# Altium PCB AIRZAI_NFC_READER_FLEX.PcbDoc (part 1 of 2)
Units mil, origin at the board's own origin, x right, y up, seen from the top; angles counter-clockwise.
Board outline 2897.24 x 5925.59 mil, 2 copper layers (Top Layer, Bottom Layer); 45 components, 43 nets, 193 pads, 92 vias.
Unrouted connection lines stored in the file: 129.
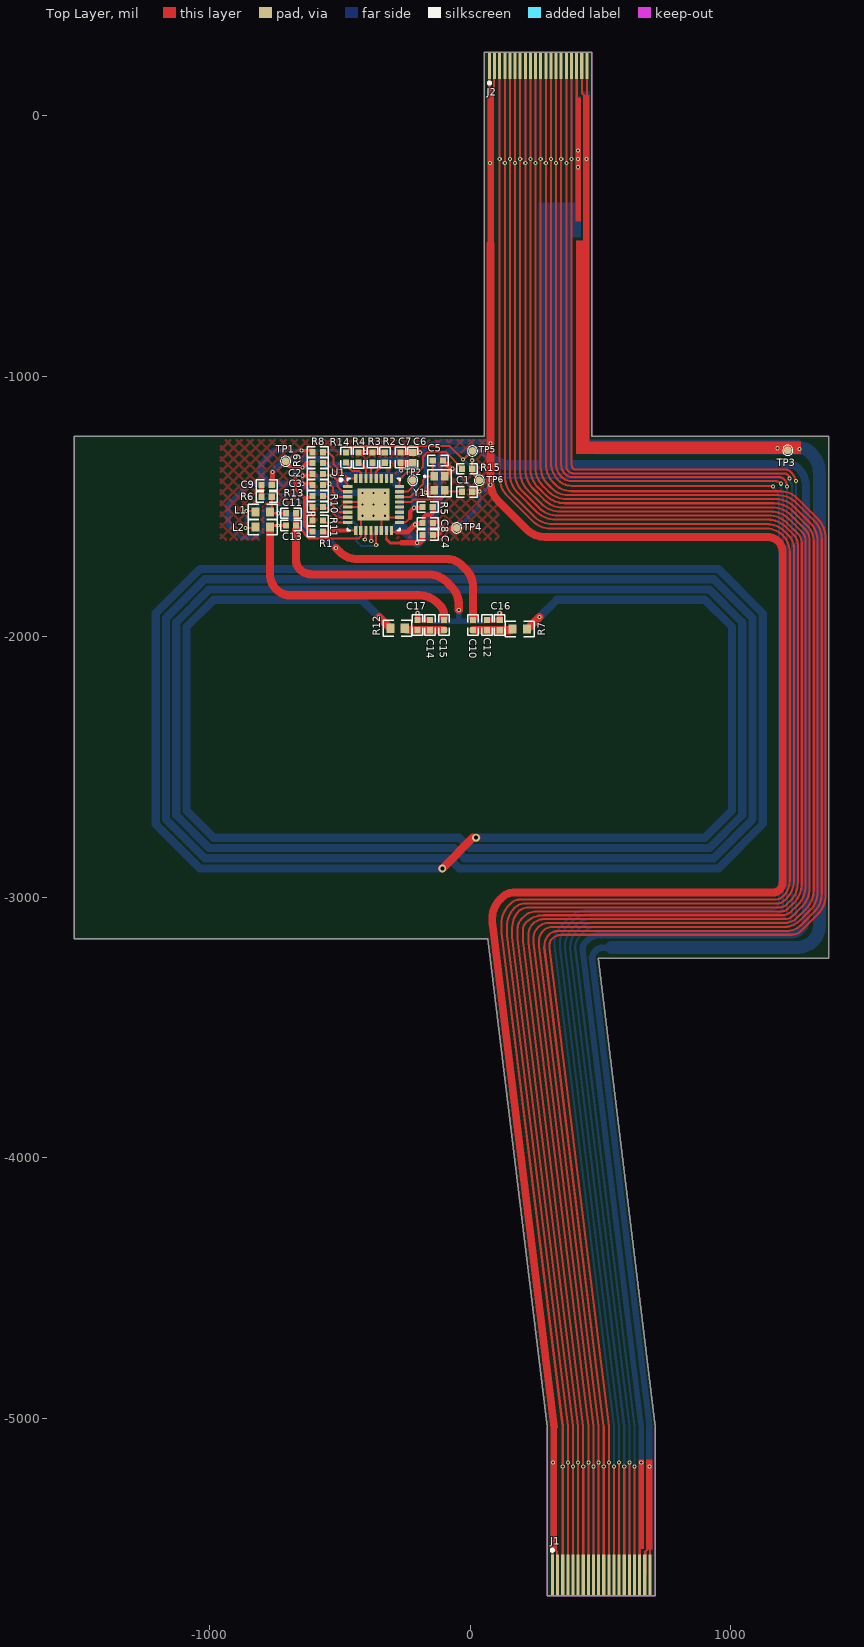
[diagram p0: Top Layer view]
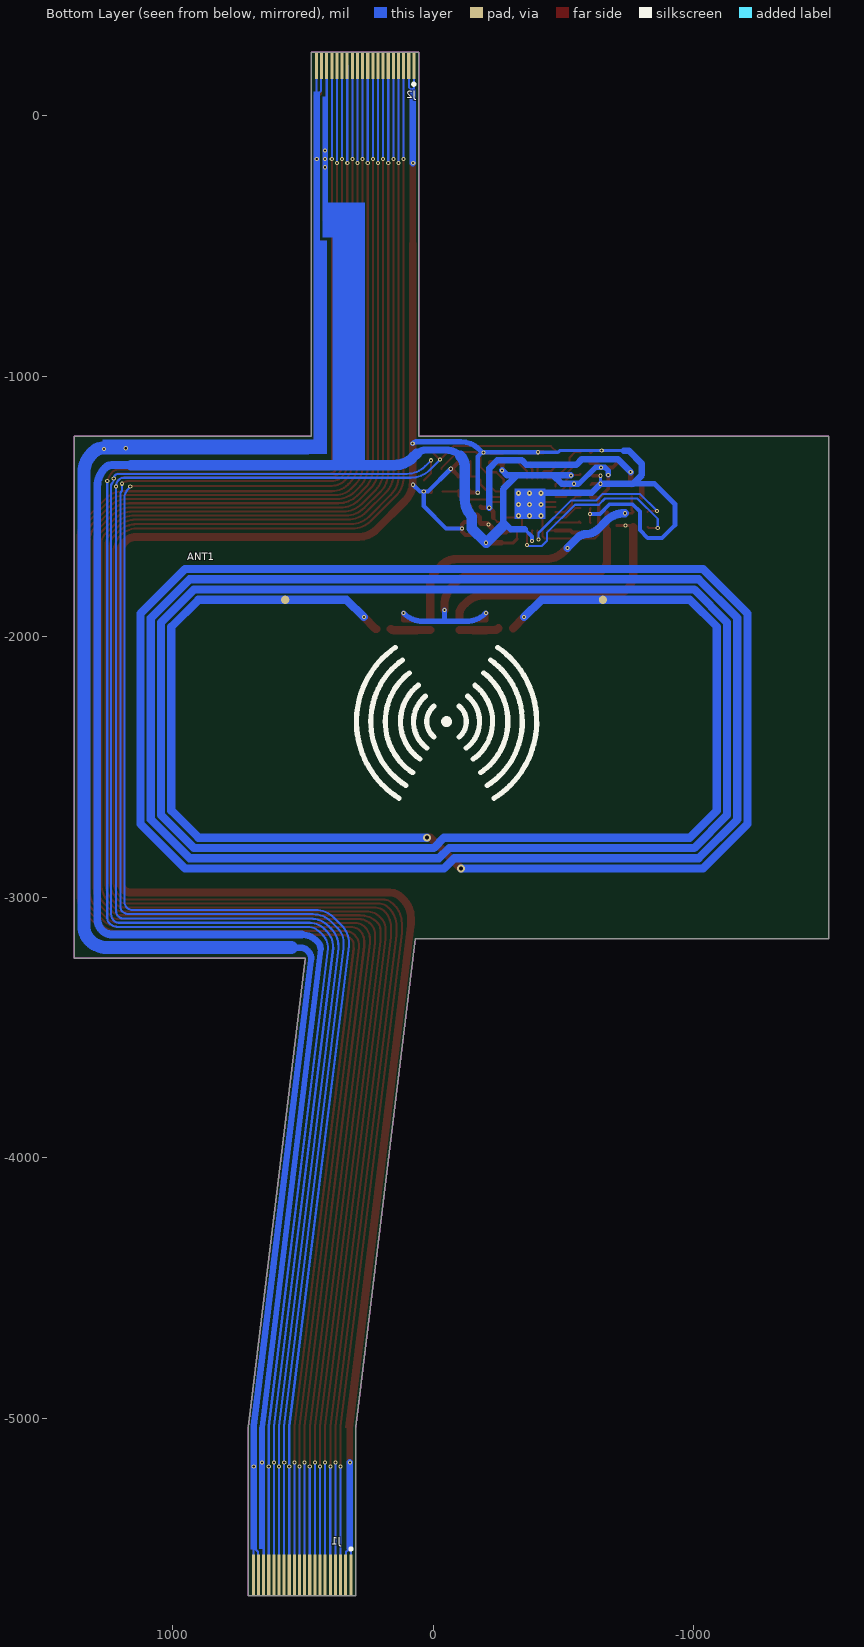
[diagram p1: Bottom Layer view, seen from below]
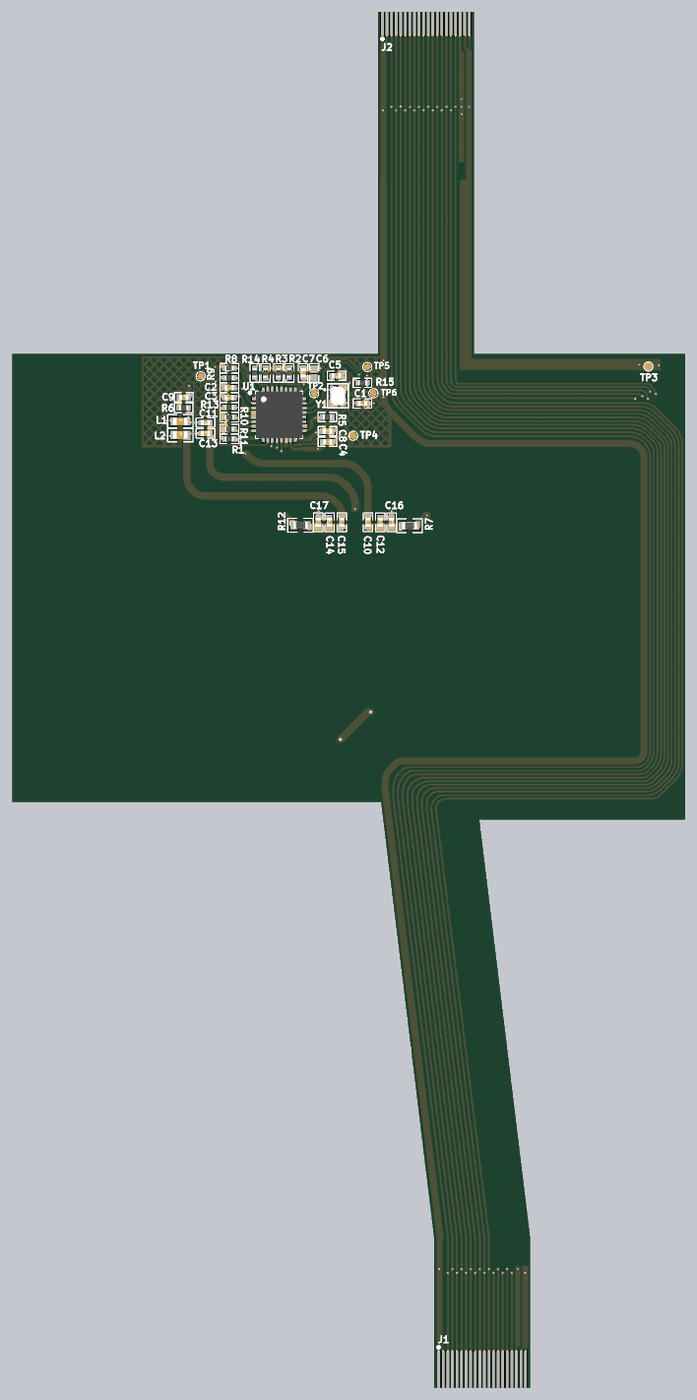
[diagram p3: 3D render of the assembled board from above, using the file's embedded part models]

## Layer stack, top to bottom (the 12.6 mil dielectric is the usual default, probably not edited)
Top Solder: solder mask 0.4, Solder Resist, Dk 3.5
Top Layer: signal copper 1.4
Dielectric 1: dielectric 12.6, FR-4, Dk 4.8
Bottom Layer: signal copper 1.4
Bottom Solder: solder mask 0.4, Solder Resist, Dk 3.5

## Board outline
-1519.83,-3158.65 -1519.83,-1229.53 54.19,-1229.53 54.19,244.09 467.57,244.09 467.57,-1229.53 1377.42,-1229.53 1377.42,-3233.99 490.88,-3233.99 490.88,-3234.01 709.7,-5033.99 709.7,-5681.5 296.31,-5681.5 296.31,-5033.99 68.33,-3158.64 68.32,-3158.65

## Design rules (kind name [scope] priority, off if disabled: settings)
Clearance Clearance_polygon_5V [OnLayer('Keep-Out Layer') vs (InNet('+5V') AND InPolygon)] p1: gap=10 ignorepadtopadclearanceinfootprint=FALSE
Clearance Clearance_POLYGON_KEEPOUT [(OnLayer('Keep-Out Layer')) vs (InNet('GND') AND InPolygon)] p2: gap=10 ignorepadtopadclearanceinfootprint=FALSE
Clearance [All] p3: gap=6 ignorepadtopadclearanceinfootprint=FALSE
MinimumSolderMaskSliver [All] p1: minsoldermaskwidth=1
PolygonConnect [All] p1: connectstyle=Direct reliefconductorwidth=10 reliefentries=4 polygonreliefangle="90 Angle" airgapwidth=10
RoomDefinition AIRZAI_NFC_READER_FLEX [InComponentClass('AIRZAI_NFC_READER_FLEX')] p1: confinementstyle=ConfineIn formatcopy=TRUE lockcomponents=FALSE outline -16741.56,-18457.69 14188.31,-18457.69 14188.31,4099.5 -16741.56,4099.5
RoutingVias [All] p1: holewidth=28 width=50 viastyle="Through Hole" minholewidth=8 minwidth=16 maxholewidth=28 maxwidth=50
SilkToSilkClearance [All] p1: silktosilkclearance=1
SilkToSolderMaskClearance [IsPad] p1: minsilkscreentomaskgap=2 clearancetoexposedcopper=TRUE
SolderMaskExpansion [All] p1: expansion=4
UnRoutedNet [All] p1: checkbadconnections=TRUE
Width [All] p1: maxlimit=100 minlimit=6 preferedwidth=10
26 further rules are at their usual default settings.

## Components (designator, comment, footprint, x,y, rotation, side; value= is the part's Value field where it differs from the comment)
ANT1 "NFC_ANT" ANTENNA-NFC-60MMX30MM -42.1,-2314.54 r180 bottom locked
C1 "12pF" 0402CAP -12,-1443.17 r180 top
C2 "0.1µF" 0402CAP -585.45,-1375.04 r180 top
C3 "0.1µF" 0402CAP -585.45,-1417.72 r180 top
C4 "0.1µF" 0402CAP -162.78,-1608.61 r0 top
C5 "12pF" 0402CAP -123.89,-1323.43 r180 top
C6 "1uF" CAPC0402(1005)60_M -220.58,-1311.81 r270 top
C7 "0.1µF" 0402CAP -267.8,-1311.69 r90 top
C8 "0.1µF" 0402CAP -162.78,-1562.61 r0 top
C9 "1nF" 0402CAP -781.38,-1416.43 r0 top
C10 "18pF" 0402CAP 11.31,-1954.52 r90 top
C11 "220pF" 0402CAP -687.95,-1525.43 r180 top
C12 "47pF" 0402CAP 64.22,-1954.87 r270 top
C13 "220pF" 0402CAP -687.95,-1572.43 r0 top
C14 "47pF" 0402CAP -154.1,-1954.87 r90 top
C15 "18pF" 0402CAP -100.99,-1954.68 r90 top
C16 "DNP" 0402CAP 113.24,-1954.86 r270 top
C17 "DNP" 0402CAP -202.78,-1954.68 r90 top
J1 "FFC Cable" FFC_PADS_MBD 493.17,-5602.76 r180 top locked
J2 "FFC Cable" FFC_PADS_LID 251.04,192.91 r180 top locked
L1 "560nH" 0603CAP -796.38,-1520.43 r0 top
L2 "560mH" 0603CAP -796.38,-1578.43 r0 top
R1 "0R" 0402 -585.42,-1595.88 r180 top
R2 "10K" 0402 -327.8,-1311.69 r270 top
R3 "10K" 0402 -374.8,-1311.69 r270 top
R4 "10K" 0402 -429.42,-1311.88 r270 top
R5 "1K" 0402 -163.26,-1501.15 r180 top
R6 "2.7K" 0402 -781.7,-1462.43 r180 top
R7 "3.3" 0603 190.22,-1969.52 r180 top
R8 "10K" 0402 -585.42,-1291.1 r180 top
R9 "10K" 0402 -585.42,-1332.88 r180 top
R10 "0R" 0402 -585.26,-1501.88 r180 top
R11 "0R" 0402 -585.42,-1552.88 r180 top
R12 "3.3" 0603 -278.78,-1967.3 r0 top
R13 "10K" 0402 -585.42,-1459.88 r180 top
R14 "0R" 0402 -476.42,-1311.62 r90 top
R15 "0R" 0402 -12,-1354.57 r0 top
TP1 "WIREPT" TP_0.9MM -708.8,-1325.99 r90 top
TP2 "WIREPT" TP_0.9MM -220.42,-1398.88 r270 top
TP3 "WIREPT" TP_0.9MM 1219,-1283.99 r90 top
TP4 "WIREPT" TP_0.9MM -52,-1581.99 r90 top
TP5 "WIREPT" TP_0.9MM 8.85,-1286.31 r90 top
TP6 "WIREPT" TP_0.9MM 35,-1399.17 r90 top
U1 "MFRC52202HN1,115" VFQFN-32-MFRC52202HN1,157 -370.78,-1491.88 r0 top
Y1 "27.12MHz" XTAL_2016 -117.78,-1410.57 r270 top

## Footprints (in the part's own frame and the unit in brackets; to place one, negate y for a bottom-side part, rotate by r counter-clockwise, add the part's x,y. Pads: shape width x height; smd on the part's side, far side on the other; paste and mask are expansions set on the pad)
0402 [mm] "Chip Resistor, Body 1.1x0.5mm, IPC High Density"
  rect 0.6x0.6 smd: 1(-0.5,0) 2(0.5,0)
  silkscreen extent -1.02,-0.51 1.02,0.51, body extent -0.5,-0.25 0.5,0.25, height 0.27
0402CAP [mm] "Chip Capacitor, Body 1.1x0.5mm, IPC High Density"
  rect 0.6x0.6 smd: 1(-0.5,0) 2(0.5,0)
  silkscreen extent -1.02,-0.51 1.02,0.51, body extent -0.5,-0.3 0.5,0.3, height 0.19
0603 [mm] "Chip Resistor, Body 1.6x0.8mm, IPC High Density"
  rect 0.8x0.9 smd: 1(-0.7,0) 2(0.7,0)
  silkscreen extent -1.4,-0.76 1.4,0.76, body extent -0.8,-0.41 0.8,0.4, height 0.37
0603CAP [mm] "Chip Capacitor, Body 1.6x0.8mm, IPC High Density"
  rect 0.8x0.9 smd: 1(-0.7,0) 2(0.7,0)
  silkscreen extent -1.4,-0.76 1.4,0.76, body extent -0.8,-0.4 0.8,0.4, height 0.29
ANTENNA-NFC-60MMX30MM [mm] "ANTENNA-ID2+10P-01"
  round 0.8 smd paste-0.8: 1(-15.494,11.6) 2(15.494,11.6)
  Top Layer lines w0.8: 15.494,11.6 23.97,11.6 26.6,8.97 26.6,-8.97 23.97,-11.6 0,-11.6 -1,-12.6 -24.404,-12.6 -27.6,-9.404 -27.6,9.404 -24.404,12.6 24.404,12.6 27.6,9.404 27.6,-9.404 24.404,-12.6 0.508,-12.6 -0.492,-13.6 -24.838,-13.6 -28.6,-9.838 -28.6,9.838 -24.838,13.6 24.838,13.6 28.6,9.838 28.6,-9.838 24.838,-13.6 1,-13.6 0,-14.6 -25.272,-14.6 -29.6,-10.272 -29.6,10.272 -25.272,14.6 25.272,14.6 29.6,10.272 29.6,-10.272 25.272,-14.6 1.651,-14.6 ; -1.651,-11.6 -23.97,-11.6 -26.6,-8.97 -26.6,8.97 -23.97,11.6 -15.494,11.6
  Bottom Layer lines w0.8: 1.651,-14.6 -1.349,-11.6 -1.651,-11.6
CAPC0402(1005)60_M [mm] "Chip Capacitor, Body 1.0x0.5mm, Height 0.6mm, IPC Low Density"
  rect 0.72x0.72 smd: 1(-0.5,0) 2(0.5,0)
  silkscreen extent -1.02,-0.51 1.02,0.51, body extent -0.55,-0.3 0.55,0.3, height 0.6
FFC_PADS_LID [mm] "(0.50mm"
  rect 0.3x2.6 smd: 1(4.5,0) 2(4,0) 3(3.5,0) 4(3,0) 5(2.5,0) 6(2,0) 7(1.5,0) 8(1,0) 9(0.5,0) 10(0,0) 11(-0.5,0) 12(-1,0) 13(-1.5,0) 14(-2,0) 15(-2.5,0) 16(-3,0) 17(-3.5,0) 18(-4,0) 19(-4.5,0) 20(-5,0)
  rect 0.3x2.6 smd far side: 1(4.5,0) 2(4,0) 3(3.5,0) 4(3,0) 5(2.5,0) 6(2,0) 7(1.5,0) 8(1,0) 9(0.5,0) 10(0,0) 11(-0.5,0) 12(-1,0) 13(-1.5,0) 14(-2,0) 15(-2.5,0) 16(-3,0) 17(-3.5,0) 18(-4,0) 19(-4.5,0) 20(-5,0)
  silkscreen extent 4.37,1.58 4.62,1.83
FFC_PADS_MBD [mm] "(0.50mm"
  rect 0.3x4 smd: 1(4.5,0) 2(4,0) 3(3.5,0) 4(3,0) 5(2.5,0) 6(2,0) 7(1.5,0) 8(1,0) 9(0.5,0) 10(0,0) 11(-0.5,0) 12(-1,0) 13(-1.5,0) 14(-2,0) 15(-2.5,0) 16(-3,0) 17(-3.5,0) 18(-4,0) 19(-4.5,0) 20(-5,0)
  rect 0.3x4 smd far side: 1(4.5,0) 2(4,0) 3(3.5,0) 4(3,0) 5(2.5,0) 6(2,0) 7(1.5,0) 8(1,0) 9(0.5,0) 10(0,0) 11(-0.5,0) 12(-1,0) 13(-1.5,0) 14(-2,0) 15(-2.5,0) 16(-3,0) 17(-3.5,0) 18(-4,0) 19(-4.5,0) 20(-5,0)
  silkscreen extent 4.39,-2.56 4.64,-2.31
TP_0.9MM [mm] "0.9MM DIA TESTPOINT"
  round 0.75 smd paste-5 mask+0.05: 1(0,0)
  silkscreen extent -0.5,-0.5 0.5,0.5
VFQFN-32-MFRC52202HN1,157 [mm]
  rect 0.9x0.31 smd: 1(-2.529,1.75) 2(-2.529,1.25) 3(-2.529,0.75) 4(-2.529,0.25) 5(-2.529,-0.25) 6(-2.529,-0.75) 7(-2.529,-1.25) 8(-2.529,-1.75) 17(2.529,-1.75) 18(2.529,-1.25) 19(2.529,-0.75) 20(2.529,-0.25) 21(2.529,0.25) 22(2.529,0.75) 23(2.529,1.25) 24(2.529,1.75)
  rect 0.31x0.9 smd: 9(-1.75,-2.529) 10(-1.25,-2.529) 11(-0.75,-2.529) 12(-0.25,-2.529) 13(0.25,-2.529) 14(0.75,-2.529) 15(1.25,-2.529) 16(1.75,-2.529) 25(1.75,2.529) 26(1.25,2.529) 27(0.75,2.529) 28(0.25,2.529) 29(-0.25,2.529) 30(-0.75,2.529) 31(-1.25,2.529) 32(-1.75,2.529)
  rect 3.1x3.1 smd: 33(0,0)
  silkscreen extent -3.32,-2.55 2.55,2.55, body extent -2.55,-2.55 2.55,2.55, height 1
XTAL_2016 [mm] "2.00mm x 1.60mm"
  rect 0.85x0.75 smd: 1(-0.675,-0.525) 2(0.675,-0.525) 3(0.675,0.525) 4(-0.675,0.525)
  silkscreen extent -1.32,-1.47 1.32,1.14, body extent -1,-0.81 1,0.79, height 0.65

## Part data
C1 C5: library part CAP, "CAP CER 12PF 50V C0G/NP0 0402", Case/Package=0402, Case Code (Metric)=1005, Dielectric=C0G, Dielectric Material=Ceramic, Manufacturer=KEMET, Manufacturer Part Number=C0402C120J5GACTU, Max Operating Temperature=125°C, Min Operating Temperature=-55°C, Package Quantity=1, Supplier Part Number 1=399-1013-6-ND, Temperature Coefficient=30ppm/°C, Tolerance=5%, Voltage=50V
C2 C3 C4 C7 C8: library part C0402-100n, "Capacitor, X7R, ±10%", Case-EIA=0402, Case-Metric=1005, Manufacturer=TDK, Manufacturer Part Number=C1005X7R1C104K, Rated Voltage="16 V", Supplier Part Number 1=445-4952-2-ND, Tolerance=±20%
C6: library part CAP, "CAP 1uF 16V ±10% 0402 (1005 Metric) Thickness 0.6mm SMD", Case/Package=0402, Case Code (Metric)=1005, Dielectric=X5R, Manufacturer="Taiyo Yuden", Manufacturer Part Number=EMK105BJ105KV-F, Max Operating Temperature=85°C, Min Operating Temperature=-55°C, Package Quantity=1, Supplier Part Number 1=587-2477-6-ND, Tolerance=10%, Voltage Rating=16V
C9: library part 56p, "CAP CER 1000PF 50V C0G/NP0 0402", Case/Package=0402, Case Code (Metric)=1005, Dielectric=C0G, Manufacturer=Murata, Manufacturer Part Number=GRM1555C1H102FA01D, Max Operating Temperature=125°C, Min Operating Temperature=-55°C, Package Quantity=1, Supplier Part Number 1=490-6189-1-ND, Tolerance=1%, Voltage=50V
C10 C15: library part 56p, "CAP CER 18PF 50V NP0 0402", Case/Package=0402, Case Code (Metric)=1005, Dielectric=C0G, Manufacturer="Kyocera AVX", Manufacturer Part Number=04025U180FAT2A, Max Operating Temperature=125°C, Min Operating Temperature=-55°C, Package Quantity=10000, Supplier Part Number 1=478-10144-1-ND, Tolerance=1%, Voltage Rating=50V
C11 C13: library part 56p, "CAP CER 220PF 50V NPO 0402", Case/Package=0402, Case Code (Metric)=1005, Dielectric=C0G, Manufacturer=Yageo, Manufacturer Part Number=CC0402FRNPO9BN221, Max Operating Temperature=125°C, Min Operating Temperature=-55°C, Supplier Part Number 1=311-3730-1-ND, Tolerance=1%, Voltage Rating=50V
C12 C14: library part 56p, "CAP CER 47PF 50V C0G/NP0 0402", Dielectric=C0G, Manufacturer=Murata, Manufacturer Part Number=GJM1555C1H470FB01D, Supplier Part Number 1=490-16376-1-ND, Tolerance=1%, Voltage Rating (DC)=50V
C16 C17: library part 56p
J1 J2: library part XF2M-2015-1A-R100, "Cable"
L1: library part Inductor, "FIXED IND 560NH 100MA 1.05 OHM", Case/Package=0603, Case Code (Metric)=1608, Current Rating=100mA, DC Resistance (DCR)=1.05R, Manufacturer=TDK, Manufacturer Part Number=MLF1608DR56JTD25, Max DC Current=30mA, Max Operating Temperature=125°C, Min Operating Temperature=-55°C, Package Quantity=4000, Ratings=AEC-Q200, Self Resonant Frequency=170MHz, Supplier Part Number 1=445-16970-1-ND, Test Frequency=25MHz, Tolerance=5%
L2: library part Inductor, "FIXED IND 560NH 100MA 1.05 OHM", Case/Package=0603, Case Code (Metric)=1608, Current Rating=100mA, DC Resistance (DCR)=1.05R, Inductance=560nH, Manufacturer=TDK, Manufacturer Part Number=MLF1608DR56JTD25, Max DC Current=30mA, Max Operating Temperature=125°C, Min Operating Temperature=-55°C, Package Quantity=4000, Ratings=AEC-Q200, Self Resonant Frequency=170MHz, Supplier Part Number 1=445-16970-1-ND, Test Frequency=25MHz, Tolerance=5%
R1 R10 R11 R14 R15: library part R0402-12k, "Resistor, ±1%, 0.063W", Case-EIA=0402, Case-Metric=1005, Manufacturer=Panasonic, Manufacturer Part Number=ERJ-2GE0R00X, Supplier Part Number 1=P0.0JTR-ND, Tolerance=±5%
R2 R3 R4 R8 R9 R13: library part R0402-12k, "Resistor 10K, ±1%, 0.063W", Case/Package=0402, Case Code (Metric)=1005, Manufacturer="Vishay Dale", Manufacturer Part Number=CRCW040210K0JNED, Max Operating Temperature=155°C, Max Power Dissipation=63mW, Min Operating Temperature=-55°C, Package Quantity=1, Resistance=10kR, Supplier Part Number 1=541-10KJDKR-ND, Temperature Coefficient=200ppm/°C, Tolerance=5%, Voltage Rating=50V
R5: library part R0402-12k, "RES SMD 1K OHM 1% 1/16W 0402", Case/Package=0402, Case Code (Metric)=1005, Manufacturer=Yageo, Manufacturer Part Number=RC0402FR-071KL, Max Operating Temperature=155°C, Min Operating Temperature=-55°C, Power Rating=62.5mW, Resistance=1kR, Supplier Part Number 1=311-1.00KLRCT-ND, Temperature Coefficient=100ppm/°C, Tolerance=1%, Voltage Rating=50V
R6: library part R0402-12k, "RES SMD 2.7K OHM 1% 1/16W 0402", Case/Package=0402, Manufacturer="Yageo Phycomp", Manufacturer Part Number=RC0402FR-072K7L, Max Operating Temperature=155°C, Min Operating Temperature=-55°C, Power Rating=63mW, Resistance=2.7kR, Supplier Part Number 1=311-2.70KLRCT-ND, Temperature Coefficient=100ppm/°C, Tolerance=1%, Voltage Rating (DC)=50V
R7 R12: library part R0402-12k, "RES SMD 3.3 OHM 1% 1/10W 0603", Case/Package=0603, Manufacturer=Yageo, Manufacturer Part Number=AC0603FR-073R3L, Max Operating Temperature=155°C, Max Power Dissipation=100mW, Min Operating Temperature=-55°C, Resistance=3.3R, Supplier Part Number 1=YAG5335CT-ND, Temperature Coefficient=200ppm/°C, Tolerance=1%
U1: library part MFRC52201HN1,157, "IC RFID READER 13.56MHZ 32HVQFN", Frequency=13.56MHz, Manufacturer="NXP Semiconductors", Max Operating Temperature=85°C, Min Operating Temperature=-25°C, Package Quantity=1500, Supplier Part Number 1=568-15200-1-ND
Y1: library part ZTB_2, "CRYSTAL 27.12MHZ 10PF SMD", Manufacturer="ECS International", Manufacturer Part Number=ECS-271.2-10-37-CKM-TR, Supplier Part Number 1=XC2511DKR-ND

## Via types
v1: diameter 16, hole 8, Top Layer to Bottom Layer, tented both sides, 81 vias
v2: diameter 19.68, hole 8, Top Layer to Bottom Layer, 9 vias
v3: diameter 30, hole 15, Top Layer to Bottom Layer, tented both sides, 2 vias

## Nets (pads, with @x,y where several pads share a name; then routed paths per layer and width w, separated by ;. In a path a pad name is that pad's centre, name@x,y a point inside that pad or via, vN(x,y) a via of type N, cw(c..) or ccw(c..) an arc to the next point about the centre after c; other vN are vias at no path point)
3V3: C2.1 C3.1 C4.1 C6.2 C7.1 J1.18 J2.18 R1.2 R9.2 R13.2 TP1.1 U1.2 U1.3 U1.12 U1.15 | length 7099
  Top Layer w8: C3.1@-565.76,-1417.72 -560.47,-1412.43 v1(-540.83,-1412.43) -526.26,-1426.99 -526.26,-1445.43 -509.34,-1462.36 U1.3@-470.35,-1462.36 ; C2.1@-565.76,-1375.04 -561.95,-1378.85 -530.96,-1378.85 -509.81,-1400 -509.81,-1421.48 -490.72,-1440.57 -472.45,-1440.57 U1.2@-470.35,-1442.67 ; U1.12@-380.62,-1591.45 -379.85,-1592.22 v1(-379.85,-1632.67) ; -321.57,-1623.13 U1.15@-321.57,-1591.45
  Top Layer w10: 408.42,-37.27 408.52,-37.17 J2.18@408.52,192.91 ; 650.54,-5490.17 650.65,-5490.28 J1.18@650.65,-5602.76
  Top Layer w12: -321.57,-1623.13 -321.57,-1625.36 -307.8,-1639.13 -262.8,-1639.13
  Top Layer w13: v1(-672.42,-1378.66) -672.42,-1431.75 -635.6,-1468.57 -635.6,-1473.67 ; R1.2@-605.11,-1595.88 -613.98,-1595.88 -635.6,-1574.27 -635.6,-1473.67 ; R13.2@-604.95,-1461.92 -607.7,-1464.67 -626.6,-1464.67 -635.6,-1473.67
  Top Layer w15: TP1.1@-711.62,-1328.81 -710.2,-1328.81 -689.75,-1349.26 v1(-644.42,-1349.26) -628.05,-1332.88 R9.2@-605.11,-1332.88
  Top Layer w17: v1(-265.11,-1360.88) C7.1@-265.11,-1336.06
  Top Layer w20: C7.1@-265.11,-1336.06 -268.8,-1332.37 C7.1@-267.8,-1331.37 -220.7,-1331.37 C6.2@-220.58,-1331.5 ; -262.8,-1639.13 -262.41,-1638.74 v1(-203.65,-1638.74) -195.26,-1638.74 -183.26,-1626.74 -183.26,-1609.41 C4.1@-182.46,-1608.61
  Bottom Layer w10: 408.42,-37.27 408.52,-37.17 J2.18@408.52,192.91 ; 650.54,-5490.17 650.65,-5490.28 J1.18@650.65,-5602.76
  Bottom Layer w15: v1(-379.85,-1632.67) -379.85,-1614.92 -352.06,-1587.13
  Bottom Layer w20: v1(-672.42,-1378.66) -672.42,-1361.88 -659.8,-1349.26 v1(-644.42,-1349.26) -623.05,-1349.26 -559.88,-1412.43 -555.39,-1412.43
  Bottom Layer w25: -555.39,-1412.43 v1(-540.83,-1412.43) -493.96,-1412.43 -461.91,-1380.38 ; v1(-529.42,-1380.38) -461.91,-1380.38 ; -352.06,-1587.13 -298.13,-1587.13 -271.32,-1560.32 -268.8,-1560.32 ; -268.8,-1573.59 -268.8,-1560.32 ; v1(-265.11,-1360.88) -284.61,-1380.38 -320.93,-1380.38 ; 432,-3197.45 cw(c466.9,-3197.45) 442.22,-3172.77 449,-3165.99 cw(c504.53,-3221.52) 504.53,-3142.99 ; -461.91,-1380.38 -320.93,-1380.38 ; -320.93,-1380.38 -268.42,-1432.88 -268.42,-1559.94 -268.8,-1560.32
  Bottom Layer w28: -104,-1304.99 cw(c-50.89,-1358.1) -50.89,-1282.99 29.2,-1282.99 cw(c29.2,-1330.79) 63,-1296.99
  Bottom Layer w30: 504.53,-3142.99 1230.96,-3142.99 ccw(c1230.96,-3084.95) 1272,-3125.99 ccw(c1230.43,-3084.42) 1289.22,-3084.42 1289.22,-2803.99 1289.22,-1422.94 ccw(c1189.22,-1422.94) 1259.93,-1352.23 1259.22,-1351.52 ccw(c1232.66,-1378.08) 1232.66,-1340.52 1160,-1340.52
  Bottom Layer w40: -268.8,-1573.59 v1(-203.65,-1638.74) -149,-1584.08 -149,-1537.99 ccw(c-214.18,-1472.81) -122,-1472.81 -122,-1348.45 cw(c-60.54,-1348.45) -104,-1304.99 ; 63,-1296.99 77.24,-1311.23 ccw(c147.95,-1240.52) 147.95,-1340.52 411,-1340.52 1160,-1340.52
  other v1: 656.74,-5170.17 414.43,-196.99 414.43,-165.99 414.43,-132.99
+5: J1.19 J1.20 J2.19 J2.20 TP3.1 | length 4568.9
  Top Layer w8: J2.19@429.98,192.91 429.98,86.02 447.89,68.11 J2.20@447.89,192.91 ; J1.19@670.33,-5602.76 672.11,-5600.98 672.11,-5513.08 690.02,-5495.17 J1.20@690.02,-5602.76
  Bottom Layer w8: J2.19@429.98,192.91 429.98,97.02 447.89,79.11 J2.20@447.89,192.91 ; J1.19@670.33,-5602.76 672.11,-5600.98 672.11,-5513.08 690.02,-5495.17 J1.20@690.02,-5602.76
  Bottom Layer w25: 468,-3236.99 cw(c511.46,-3236.99) 480.73,-3206.26 483,-3203.99 cw(c507.14,-3228.13) 507.14,-3193.99 538,-3192.99
  Bottom Layer w40: 451.42,-1262.17 ccw(c482.8,-1230.79) 482.8,-1275.17
  Bottom Layer w50: 482.8,-1274.17 1264.76,-1274.17 cw(c1264.76,-1329.98) 1304.22,-1290.52 1311.25,-1297.55 cw(c1240.54,-1368.26) 1340.54,-1368.26 1340.54,-2803.99 1340.54,-3111.57 cw(c1263.58,-3111.57) 1318,-3165.99 cw(c1252.85,-3100.85) 1252.85,-3192.98 543.22,-3192.98 543,-3193.19
  other v1: 688.74,-5186.17 1264,-1278.99 1180,-1275.99 446.61,-165.27
ACCELERO_INT: J1.14 J2.14 | length 8240.3
  Top Layer w8: J2.14@329.78,192.91 329.78,-1336.05 ccw(c400.67,-1336.05) 350.54,-1386.17 ccw(c389.34,-1347.37) 389.34,-1402.25 1170.47,-1402.25 cw(c1170.47,-1435.52) v1(1194,-1411.99) ; J1.14@571.91,-5602.76 v1@571.91,-5170.17
  Bottom Layer w8: v1@329.78,-181.27 J2.14@329.78,192.91 ; 344.17,-3194.99 344.17,-3194.34 ; J1.14@571.91,-5602.76 571.91,-5032.35 ; 572.1,-5032.35 344.25,-3194.98 344.17,-3194.34 ; v1(1194,-1411.99) 1194,-1436.16 ccw(c1200.83,-1436.16) 1196,-1440.99 cw(c1186.34,-1450.65) 1200,-1450.65 1200,-3039.51 cw(c1179.51,-3039.51) 1194,-3053.99 cw(c1167.44,-3027.44) 1167.44,-3064.99 461.42,-3064.99 ccw(c461.42,-3164.99) 390.71,-3094.28 366,-3118.99 ccw(c418.71,-3171.7) 344.17,-3171.7 344.17,-3194.34
  other v1: 571.54,-5170.17 329.42,-181.27
ADC_CH1: J1.5 J2.5 | length 8582.8
  Top Layer w8: J2.5@152.61,192.91 152.61,-1375.82 ccw(c252.61,-1375.82) 181.9,-1446.53 256.25,-1520.88 ccw(c326.96,-1450.17) 326.96,-1550.17 1142.15,-1550.17 cw(c1142.15,-1650.17) 1212.86,-1579.46 1242,-1608.61 cw(c1203.37,-1647.23) 1258,-1647.23 1258,-2943.98 cw(c1158.99,-2943.98) 1229,-3013.99 1215.75,-3027.24 cw(c1187.38,-2998.87) 1187.38,-3038.99 227.28,-3038.99 ccw(c227.28,-3107.28) 188.41,-3051.14 ccw(c253.81,-3116.54) 161.32,-3116.54 161.32,-3151.69 394.54,-5032.35 v1(394.54,-5186.17) ; J1.5@394.74,-5602.76 v1@394.74,-5186.17
  Bottom Layer w8: v1@152.61,-164.99 J2.5@152.61,192.91 ; J1.5@394.74,-5602.76 v1@394.74,-5186.17
  other v1: 152.42,-165.27
CAP1_TOUCH_OUT: J1.7 J2.7 | length 8555.3
  Top Layer w8: J2.7@191.98,192.91 191.98,-1366.19 ccw(c291.98,-1366.19) 221.27,-1436.9 274.25,-1489.88 ccw(c344.96,-1419.17) 344.96,-1519.17 1153.76,-1519.17 cw(c1153.76,-1619.17) 1224.47,-1548.46 1275,-1598.99 cw(c1243.62,-1630.38) 1288,-1630.38 1288,-2957.57 cw(c1188,-2957.57) 1258.71,-3028.28 1231,-3055.99 cw(c1199.62,-3024.61) 1199.62,-3068.99 281.6,-3068.99 ccw(c281.6,-3164.59) 214,-3096.99 ccw(c241.72,-3124.72) 202.52,-3124.72 202.52,-3166.42 433.91,-5032.35 v1@433.91,-5186.17 ; J1.7@434.11,-5602.76 v1(434.11,-5186.17)
  Bottom Layer w8: v1@191.98,-164.99 J2.7@191.98,192.91 ; J1.7@434.11,-5602.76 v1(434.11,-5186.17)
  other v1: 191.98,-165.27
CAP2_TOUCH_OUT: J1.8 J2.8 | length 8578.1
  Top Layer w8: J2.8@211.67,192.91 211.67,-1359.88 ccw(c311.67,-1359.88) 240.96,-1430.59 284.25,-1473.88 ccw(c354.96,-1403.17) 354.96,-1503.17 1160.76,-1503.17 cw(c1160.76,-1603.17) 1231.47,-1532.46 1285.33,-1586.32 cw(c1242.64,-1628.99) 1303,-1628.99 1303,-2965.57 cw(c1203,-2965.57) 1273.71,-3036.28 1238,-3071.99 cw(c1209.03,-3043.02) 1209.03,-3083.99 284.26,-3083.99 ccw(c284.26,-3146.59) 240,-3102.33 ccw(c280.65,-3142.97) 223.16,-3142.97 223.16,-3172.6 ; 223.16,-3174.01 223.16,-3172.6 ; J1.8@453.8,-5602.76 v1(453.8,-5170.17) 453.8,-5032.35 223.34,-3173.99 223.16,-3172.6
  Bottom Layer w8: v1(211.67,-181.27) J2.8@211.67,192.91 ; J1.8@453.8,-5602.76 v1(453.8,-5170.17)
EN: J1.17 J2.17 | length 8213.8
  Top Layer w8: J2.17@388.83,192.91 388.83,-1336.56 ccw(c415.15,-1336.56) 396.53,-1355.16 ccw(c403.79,-1347.93) 403.79,-1358.17 1211.12,-1358.17 cw(c1211.12,-1384.87) 1230,-1365.99 cw(c1172.06,-1423.93) v1@1251.08,-1402.25 ; J1.17@630.96,-5602.76 v1(630.96,-5186.17)
  Bottom Layer w8: v1@388.83,-164.99 J2.17@388.83,192.91 ; 403,-3196.25 cw(c476.05,-3196.25) 424.4,-3144.6 436,-3132.99 cw(c482.57,-3179.56) 482.57,-3113.7 1208.49,-3113.7 ccw(c1208.49,-3063.48) 1244,-3098.99 ccw(c1226.91,-3081.9) 1251.08,-3081.9 v1(1251.08,-1401.99) ; 403.26,-3196.22 630.96,-5032.35 J1.17@630.96,-5602.76
  other v1: 388.83,-165.27
GND: C1.1 C2.2 C3.2 C4.2 C5.1 C6.1 C7.2 C8.2 C11.1 C12.1 C13.2 C14.2 C16.1 C17.2 J1.1 J1.2 J2.1 J2.2 R2.1 R3.1 R4.1 R8.2 R10.2 R11.2 TP4.1 U1.4 U1.5 U1.10 U1.14 U1.18 U1.33 Y1.2 Y1.4 | length 13004.5
  Top Layer w8: C13.2@-668.26,-1572.43 -664.56,-1572.43 -635.6,-1601.39 -635.6,-1607.16 -619.73,-1623.03 -428.93,-1623.03 -419.99,-1614.09 U1.10@-419.99,-1591.45 -419.99,-1541.1 v2(-414.09,-1535.19) U1.33@-380.62,-1501.73 ; C2.2@-611.66,-1381.57 C2.2@-605.13,-1375.04 ; C3.2@-610.43,-1412.43 C3.2@-605.13,-1417.72 ; R10.2@-605.14,-1505.92 cw(c-611.27,-1512.04) -602.6,-1512.04 v1(-602.6,-1527.88) -602.6,-1559.57 R11.2@-604.95,-1561.92 ; U1.5@-470.35,-1501.73 U1.33@-380.62,-1501.73 ; U1.4@-470.35,-1482.04 U1.33@-414.09,-1482.04 ; U1.14@-341.25,-1591.45 -341.25,-1548.91 -327.54,-1535.19 v2(-327.47,-1535.19) ; U1.18@-271.21,-1541.1 -321.57,-1541.1 v2(-327.47,-1535.19) ; 73.87,-32.27 J2.1@73.87,192.91 ; 78.3,95.3 91.78,108.78 J2.2@91.78,192.91 ; J1.1@316,-5602.76 316,-5495.17 ; 320.43,-5499.6 333.91,-5513.08 J1.2@333.91,-5600.98 ; U1.33@-380.62,-1501.73 v2(-370.78,-1491.88) v2(-327.47,-1535.19)
  Top Layer w12: v1(-647.36,-1285.07) -611.14,-1285.07 R8.2@-605.11,-1291.1 ; v1@-637.26,-1412.43 C3.2@-610.43,-1412.43 ; v1@-637.26,-1381.57 C2.2@-611.66,-1381.57
  Top Layer w15: -668.26,-1589.52 C13.2@-668.26,-1572.43
  Top Layer w16: v1(-403.07,-1291.1) -421.65,-1291.1 -422.55,-1292 R3.1@-374.8,-1292 R2.1@-327.8,-1292 ; v1(-171.6,-1446.67) -170.81,-1445.88 -145.23,-1445.88 -138.46,-1439.11 Y1.2@-138.46,-1437.14 ; C4.2@-143.09,-1608.61 -124.55,-1608.61 -111.6,-1595.65 v1(-111.6,-1583.67) ; C8.2@-143.09,-1562.61 -139.78,-1559.3 -120.97,-1559.3 -111.6,-1568.67 v1(-111.6,-1583.67) ; C5.1@-104.2,-1323.43 v1@-73.06,-1354.57 ; Y1.4@-97.09,-1383.99 -97.09,-1382.03 v1@-69.64,-1354.57 ; TP4.1@-52,-1581.99 -53.67,-1583.67 v1(-111.6,-1583.67) ; C1.1@7.69,-1443.17 8.48,-1442.37 v1(35.9,-1442.37)
  Top Layer w18: C7.2@-267.8,-1292 -267.74,-1292.06 -220.64,-1292.06 C6.1@-220.58,-1292.13 -219.36,-1293.34 -217.9,-1291.88 v1(-193,-1291.88)
  Top Layer w20: C13.2@-668.26,-1572.43 C11.1@-668.26,-1525.43 ; v1(-202.51,-1907.99) -202.51,-1934.72 C17.2@-202.78,-1934.99 -202.68,-1935.09 -154.19,-1935.09 C14.2@-154.1,-1935.19 ; C12.1@64.22,-1935.18 C16.1@113.24,-1935.18 v1(113.24,-1908.45)
  Top Layer w25: 78.3,-492.27 78.3,95.3 ; 320.43,-5499.6 320.43,-5035.17
  Top Layer w30: 78.3,-492.27 v1(78.3,-1257.99) 78.3,-1407.51 ccw(c178.3,-1407.51) 107.59,-1478.22 216.25,-1586.88 ccw(c286.96,-1516.17) 286.96,-1616.17 1138.57,-1616.17 cw(c1138.57,-1680.42) 1184,-1634.99 cw(c1145.37,-1673.62) 1200,-1673.62 1200,-2940.61 cw(c1155.62,-2940.61) 1187.06,-2971.93 cw(c1162.86,-2947.85) 1162.86,-2981.99 166.46,-2981.99 ccw(c166.46,-3043.45) 123,-2999.99 114.29,-3008.7 ccw(c185,-3079.41) 85,-3079.41 85,-3102.99
  Top Layer w31.5: -668.26,-1589.52 -668.26,-1707.96 ccw(c-622.22,-1707.96) -654.78,-1740.52 ccw(c-606.5,-1692.24) -606.5,-1760.52 -160.2,-1760.52 cw(c-160.2,-1860.52) -89.49,-1789.81 -73.07,-1806.23 cw(c-143.78,-1876.94) -43.78,-1876.94 v1(-43.78,-1897.52)
  Bottom Layer w8: 73.87,-32.27 J2.1@73.87,192.91 ; 77.42,94.42 91.78,108.78 J2.2@91.78,192.91 ; J1.1@316,-5602.76 316,-5495.17 ; 319.54,-5498.72 333.91,-5513.08 J1.2@333.91,-5600.98
  Bottom Layer w12: -732.61,-1285.07 v1(-647.36,-1285.07) -485.92,-1285.07 -479.89,-1291.1 v1(-403.07,-1291.1) ; v1(-643.26,-1412.43) v1(-643.26,-1381.57)
  Bottom Layer w15: -929,-1570.11 -879.11,-1620 -824,-1620 -794,-1590 -794,-1519 -766,-1491 -677,-1491 -640.12,-1527.88 v1(-602.6,-1527.88)
  Bottom Layer w16: v1(-403.07,-1291.1) -187.98,-1291.1 -171.6,-1307.48 v1(-171.6,-1446.67) ; v1(-111.6,-1583.67) -49.67,-1583.67 35.9,-1498.09 v1(35.9,-1442.37) ; v1(-67.78,-1354.57) 20.03,-1442.37 v1(35.9,-1442.37) ; v1(77.24,-1415.99) 50.86,-1442.37 v1(35.9,-1442.37)
  Bottom Layer w20: -929,-1570.11 -929,-1491 -850.43,-1412.43 -767.88,-1412.43 ; v1(-202.51,-1907.99) -199.27,-1911.23 ccw(c-128.56,-1840.52) -128.56,-1940.52 -43.78,-1940.52 ; v1@-187.98,-1291.1 -177.15,-1280.28 cw(c-106.44,-1350.99) -106.44,-1250.99 61.4,-1250.99 cw(c61.4,-1274.89) v1(78.3,-1257.99) ; v1(-43.78,-1897.52) -43.78,-1940.52 ; v1(113.24,-1908.45) 110.46,-1911.23 cw(c39.75,-1840.52) 39.75,-1940.52 -43.78,-1940.52
  Bottom Layer w25: -732.61,-1285.07 -751.08,-1285.07 -802,-1335.99 -802,-1378.31 -767.88,-1412.43 v1(-643.26,-1412.43) -609.03,-1446.67 -416,-1446.67 v2(-414.09,-1448.58) ; v1@77.42,-181.27 77.42,94.42 ; 319.54,-5498.72 v1@319.54,-5170.17
  other v1: 318.54,-5170.17 76.42,-181.27
  other v2: -370.78,-1535.19 -414.09,-1491.88 -327.47,-1491.88 -370.78,-1448.58 -327.47,-1448.58
"LED Str CLK": J1.10 J2.10 | length 8551.2
  Top Layer w8: J2.10@251.04,192.91 251.04,-1351.25 ccw(c351.04,-1351.25) 280.33,-1421.96 301.54,-1443.17 ccw(c369.14,-1375.58) 369.14,-1471.17 1172.76,-1471.17 cw(c1172.76,-1571.17) 1243.47,-1500.46 1304.71,-1561.7 cw(c1234,-1632.41) 1334,-1632.41 1334,-2979.57 cw(c1234,-2979.57) 1304.71,-3050.28 1264.83,-3090.16 cw(c1208,-3033.33) 1208,-3113.7 315.5,-3113.7 ccw(c315.5,-3162.49) 281,-3127.99 ccw(c321.13,-3168.12) 264.38,-3168.12 264.38,-3186.89 ; 264.31,-3186.95 493.17,-5032.35 v1(493.17,-5170.17) J1.10@493.17,-5602.76
  Bottom Layer w8: v1(251.04,-181.27) J2.10@251.04,192.91 ; J1.10@493.17,-5602.76 v1(493.17,-5170.17)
